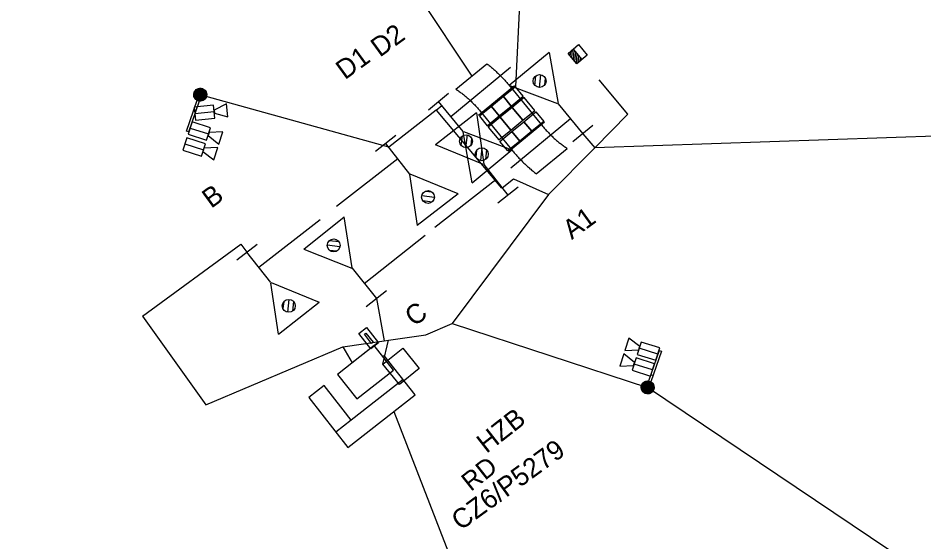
# Model space of a CAD drawing. Extents: x -651112 to -650977, y -1098325 to -1098185.
# Drawn here: x -651091.5 to -651021.5, y -1098284.8 to -1098244.3 of the extents above; entities that cross this region are included whole.
import ezdxf

# ---------------------------------------------------------------- set-up
doc = ezdxf.new("R2010")
doc.units = 0
for name, color, linetype in [('PS 11-01-31', 7, 'Continuous'), ('PS 11-02-41', 7, 'Continuous'), ('SO 01-86-01', 7, 'Continuous'), ('SO 11-13-01', 7, 'Continuous'), ('SO 11-50-01', 7, 'Continuous')]:
    doc.layers.add(name, color=color, linetype=linetype)

msp = doc.modelspace()

# ---------------------------------------------------------------- linework, layer by layer
at = {"layer": 'PS 11-01-31'}
for p, q in [((-651049.004, -1098247.056), (-651048.196, -1098246.386)), ((-651049.004, -1098247.056), (-651048.6, -1098246.721)), ((-651049.004, -1098247.056), (-651048.6, -1098246.721)), ((-651048.709, -1098247.412), (-651048.648, -1098246.761)), ((-651048.6, -1098246.721), (-651047.93, -1098247.53)), ((-651048.6, -1098246.721), (-651047.93, -1098247.53)), ((-651048.196, -1098246.386), (-651047.525, -1098247.195)), ((-651050.456, -1098246.985), (-651053.538, -1098249.535)), ((-651050.456, -1098246.985), (-651049.766, -1098250.925)), ((-651048.334, -1098247.865), (-651049.004, -1098247.056)), ((-651048.334, -1098247.865), (-651049.004, -1098247.056)), ((-651048.334, -1098247.865), (-651049.004, -1098247.056)), ((-651048.946, -1098247.126), (-651048.934, -1098246.998)), ((-651048.827, -1098247.27), (-651048.791, -1098246.88)), ((-651048.59, -1098247.555), (-651048.521, -1098246.816)), ((-651048.472, -1098247.698), (-651048.403, -1098246.959)), ((-651048.353, -1098247.841), (-651048.284, -1098247.102)), ((-651047.525, -1098247.195), (-651048.334, -1098247.865)), ((-651048.215, -1098247.766), (-651048.166, -1098247.245)), ((-651048.072, -1098247.647), (-651048.048, -1098247.387)), ((-651058.06, -1098251.939), (-651053.436, -1098248.116)), ((-651047.93, -1098247.53), (-651048.334, -1098247.865)), ((-651047.93, -1098247.53), (-651048.334, -1098247.865)), ((-651051.562, -1098249.539), (-651051.491, -1098248.791)), ((-651051.2, -1098249.693), (-651051.106, -1098248.707)), ((-651049.798, -1098250.954), (-651053.538, -1098249.535)), ((-651050.805, -1098249.498), (-651050.755, -1098248.975)), ((-651044.373, -1098251.75), (-651046.585, -1098249.116)), ((-651059.787, -1098251.42), (-651058.245, -1098250.146)), ((-651057.105, -1098253.095), (-651059.016, -1098250.783)), ((-651049.766, -1098250.957), (-651047.854, -1098253.269)), ((-651059.188, -1098251.441), (-651062.859, -1098254.301)), ((-651056.078, -1098251.663), (-651059.229, -1098254.128)), ((-651059.184, -1098251.442), (-651058.764, -1098251.093)), ((-651059.184, -1098251.442), (-651054.14, -1098257.484)), ((-651056.078, -1098251.663), (-651055.496, -1098255.62)), ((-651048.81, -1098252.113), (-651053.433, -1098255.937)), ((-651046.938, -1098254.352), (-651044.373, -1098251.75)), ((-651047.083, -1098252.631), (-651048.624, -1098253.906)), ((-651062.296, -1098253.406), (-651063.871, -1098254.638)), ((-651057.253, -1098254.186), (-651057.162, -1098253.44)), ((-651056.416, -1098257.067), (-651057.104, -1098253.127)), ((-651057.072, -1098253.098), (-651053.333, -1098254.518)), ((-651056.896, -1098254.349), (-651056.776, -1098253.366)), ((-651056.496, -1098254.166), (-651056.432, -1098253.643)), ((-651047.854, -1098253.269), (-651046.938, -1098254.352)), ((-651019.677, -1098253.419), (-651046.938, -1098254.352)), ((-651061.234, -1098256.384), (-651063.083, -1098254.022)), ((-651055.529, -1098255.648), (-651059.229, -1098254.128)), ((-651055.671, -1098254.36), (-651055.765, -1098255.345)), ((-651050.505, -1098257.97), (-651046.938, -1098254.352)), ((-651056.416, -1098257.067), (-651053.333, -1098254.518)), ((-651056.066, -1098254.554), (-651056.116, -1098255.077)), ((-651055.309, -1098254.513), (-651055.38, -1098255.261)), ((-651062.159, -1098255.203), (-651066.884, -1098258.901)), ((-651055.497, -1098255.652), (-651053.648, -1098258.015)), ((-651061.238, -1098256.417), (-651060.652, -1098260.373)), ((-651057.502, -1098257.908), (-651061.204, -1098256.391)), ((-651054.573, -1098256.833), (-651059.298, -1098260.53)), ((-651054.083, -1098257.463), (-651053.21, -1098256.76)), ((-651053.21, -1098256.76), (-651050.505, -1098257.97)), ((-651057.502, -1098257.908), (-651060.652, -1098260.373)), ((-651060.032, -1098257.711), (-651059.51, -1098257.775)), ((-651050.505, -1098257.97), (-651057.947, -1098267.94)), ((-651052.861, -1098257.398), (-651054.436, -1098258.631)), ((-651060.306, -1098258.055), (-651059.323, -1098258.175)), ((-651060.233, -1098258.442), (-651059.488, -1098258.533)), ((-651072.886, -1098263.596), (-651068.16, -1098259.899)), ((-651069.424, -1098262.182), (-651066.297, -1098259.687)), ((-651065.674, -1098263.638), (-651066.297, -1098259.687)), ((-651064.742, -1098264.843), (-651060.052, -1098261.101)), ((-651081.875, -1098267.363), (-651074.288, -1098261.815)), ((-651074.598, -1098263.031), (-651073.023, -1098261.799)), ((-651074.288, -1098261.815), (-651073.81, -1098262.415)), ((-651069.424, -1098262.182), (-651065.708, -1098263.664)), ((-651066.621, -1098262.008), (-651067.605, -1098261.897)), ((-651066.697, -1098261.622), (-651067.444, -1098261.538)), ((-651071.962, -1098264.778), (-651073.81, -1098262.415)), ((-651066.892, -1098262.355), (-651067.415, -1098262.296)), ((-651065.677, -1098263.67), (-651063.807, -1098266.015)), ((-651071.38, -1098268.767), (-651071.962, -1098264.81)), ((-651071.929, -1098264.782), (-651068.23, -1098266.302)), ((-651064.588, -1098266.639), (-651063.025, -1098265.392)), ((-651071.38, -1098268.767), (-651068.23, -1098266.302)), ((-651070.963, -1098266.264), (-651071.027, -1098266.786)), ((-651070.563, -1098266.081), (-651070.683, -1098267.063)), ((-651070.205, -1098266.244), (-651070.296, -1098266.989)), ((-651063.807, -1098266.015), (-651063.212, -1098269.281)), ((-651081.875, -1098267.363), (-651076.998, -1098274.237)), ((-651059.998, -1098268.811), (-651057.947, -1098267.94)), ((-651057.947, -1098267.94), (-651057.947, -1098267.94)), ((-651062.885, -1098269.233), (-651059.998, -1098268.811)), ((-651076.998, -1098274.237), (-651066.397, -1098269.747)), ((-651063.972, -1098269.653), (-651066.807, -1098271.871)), ((-651066.397, -1098269.747), (-651063.212, -1098269.281)), ((-651066.397, -1098269.747), (-651065.667, -1098270.979)), ((-651063.676, -1098269.422), (-651065.667, -1098270.979)), ((-651062.493, -1098271.543), (-651063.972, -1098269.653)), ((-651063.21, -1098269.28), (-651062.884, -1098269.233)), ((-651066.807, -1098271.871), (-651065.328, -1098273.761)), ((-651065.328, -1098273.761), (-651062.493, -1098271.543))]:
    msp.add_line(p, q, dxfattribs=at)
for centre in [(-651051.2, -1098249.196), (-651056.883, -1098253.852), (-651055.671, -1098254.856), (-651059.821, -1098258.162), (-651067.107, -1098261.906), (-651070.576, -1098266.577)]:
    msp.add_circle(centre, 0.5, dxfattribs=at)
at = {"layer": 'PS 11-02-41'}
for p, q in [((-651062.859, -1098254.301), (-651077.417, -1098250.253)), ((-651078.478, -1098253.061), (-651077.661, -1098250.677)), ((-651078.302, -1098253.121), (-651077.485, -1098250.737)), ((-651077.83, -1098251.169), (-651077.654, -1098251.229)), ((-651077.825, -1098251.715), (-651076.333, -1098251.561)), ((-651076.331, -1098251.583), (-651076.335, -1098251.54)), ((-651076.335, -1098251.546), (-651076.332, -1098251.577)), ((-651078.302, -1098253.121), (-651078.478, -1098253.061)), ((-651078.198, -1098252.832), (-651076.769, -1098253.288)), ((-651076.775, -1098253.308), (-651076.763, -1098253.268)), ((-651076.764, -1098253.273), (-651076.774, -1098253.303)), ((-651078.598, -1098254.06), (-651077.169, -1098254.516)), ((-651077.175, -1098254.536), (-651077.163, -1098254.496)), ((-651077.164, -1098254.501), (-651077.174, -1098254.531)), ((-651057.947, -1098267.94), (-651042.851, -1098272.885)), ((-651063.307, -1098271.08), (-651062.884, -1098269.233)), ((-651043.493, -1098269.828), (-651043.506, -1098269.869)), ((-651043.505, -1098269.864), (-651043.495, -1098269.833)), ((-651042.071, -1098270.305), (-651043.5, -1098269.849)), ((-651041.966, -1098270.017), (-651042.783, -1098272.401)), ((-651041.789, -1098270.077), (-651042.607, -1098272.461)), ((-651041.966, -1098270.017), (-651041.789, -1098270.077)), ((-651043.893, -1098271.057), (-651043.906, -1098271.098)), ((-651043.905, -1098271.093), (-651043.895, -1098271.062)), ((-651042.471, -1098271.534), (-651043.9, -1098271.078)), ((-651042.438, -1098271.969), (-651042.614, -1098271.909)), ((-650996.009, -1098304.415), (-651042.851, -1098272.885))]:
    msp.add_line(p, q, dxfattribs=at)
for points in [[(-651077.792, -1098249.922), (-651077.9, -1098250.381), (-651077.916, -1098250.284), (-651077.792, -1098249.922)], [(-651077.792, -1098249.922), (-651077.916, -1098250.284), (-651077.849, -1098250.002), (-651077.792, -1098249.922)], [(-651077.849, -1098250.002), (-651077.916, -1098250.284), (-651077.912, -1098250.186), (-651077.849, -1098250.002)], [(-651077.849, -1098250.002), (-651077.912, -1098250.186), (-651077.89, -1098250.091), (-651077.849, -1098250.002)], [(-651077.72, -1098249.855), (-651077.866, -1098250.473), (-651077.9, -1098250.381), (-651077.72, -1098249.855)], [(-651077.72, -1098249.855), (-651077.9, -1098250.381), (-651077.792, -1098249.922), (-651077.72, -1098249.855)], [(-651077.637, -1098249.804), (-651077.815, -1098250.556), (-651077.866, -1098250.473), (-651077.637, -1098249.804)], [(-651077.637, -1098249.804), (-651077.866, -1098250.473), (-651077.72, -1098249.855), (-651077.637, -1098249.804)], [(-651077.545, -1098249.77), (-651077.748, -1098250.628), (-651077.815, -1098250.556), (-651077.545, -1098249.77)], [(-651077.545, -1098249.77), (-651077.815, -1098250.556), (-651077.637, -1098249.804), (-651077.545, -1098249.77)], [(-651077.448, -1098249.754), (-651077.668, -1098250.685), (-651077.748, -1098250.628), (-651077.448, -1098249.754)], [(-651077.448, -1098249.754), (-651077.748, -1098250.628), (-651077.545, -1098249.77), (-651077.448, -1098249.754)], [(-651077.35, -1098249.757), (-651077.668, -1098250.685), (-651077.448, -1098249.754), (-651077.35, -1098249.757)], [(-651077.35, -1098249.757), (-651077.579, -1098250.726), (-651077.668, -1098250.685), (-651077.35, -1098249.757)], [(-651077.255, -1098249.78), (-651077.579, -1098250.726), (-651077.35, -1098249.757), (-651077.255, -1098249.78)], [(-651077.255, -1098249.78), (-651077.484, -1098250.749), (-651077.579, -1098250.726), (-651077.255, -1098249.78)], [(-651077.166, -1098249.821), (-651077.484, -1098250.749), (-651077.255, -1098249.78), (-651077.166, -1098249.821)], [(-651077.166, -1098249.821), (-651077.386, -1098250.752), (-651077.484, -1098250.749), (-651077.166, -1098249.821)], [(-651077.086, -1098249.878), (-651077.386, -1098250.752), (-651077.166, -1098249.821), (-651077.086, -1098249.878)], [(-651077.086, -1098249.878), (-651077.289, -1098250.736), (-651077.386, -1098250.752), (-651077.086, -1098249.878)], [(-651077.019, -1098249.95), (-651077.289, -1098250.736), (-651077.086, -1098249.878), (-651077.019, -1098249.95)], [(-651077.019, -1098249.95), (-651077.197, -1098250.702), (-651077.289, -1098250.736), (-651077.019, -1098249.95)], [(-651076.968, -1098250.033), (-651077.197, -1098250.702), (-651077.019, -1098249.95), (-651076.968, -1098250.033)], [(-651076.968, -1098250.033), (-651077.114, -1098250.651), (-651077.197, -1098250.702), (-651076.968, -1098250.033)], [(-651076.934, -1098250.125), (-651077.114, -1098250.651), (-651076.968, -1098250.033), (-651076.934, -1098250.125)], [(-651076.934, -1098250.125), (-651077.042, -1098250.584), (-651077.114, -1098250.651), (-651076.934, -1098250.125)], [(-651076.918, -1098250.222), (-651077.042, -1098250.584), (-651076.934, -1098250.125), (-651076.918, -1098250.222)], [(-651076.918, -1098250.222), (-651076.985, -1098250.504), (-651077.042, -1098250.584), (-651076.918, -1098250.222)], [(-651076.921, -1098250.32), (-651076.985, -1098250.504), (-651076.918, -1098250.222), (-651076.921, -1098250.32)], [(-651076.921, -1098250.32), (-651076.944, -1098250.415), (-651076.985, -1098250.504), (-651076.921, -1098250.32)], [(-651076.346, -1098251.437), (-651076.32, -1098251.686), (-651075.287, -1098251.956), (-651075.39, -1098250.962), (-651076.346, -1098251.437)], [(-651077.877, -1098251.218), (-651077.774, -1098252.212), (-651076.282, -1098252.059), (-651076.384, -1098251.064), (-651077.877, -1098251.218)], [(-651077.877, -1098251.218), (-651077.774, -1098252.212), (-651076.282, -1098252.059), (-651076.384, -1098251.064), (-651077.877, -1098251.218)], [(-651078.046, -1098252.356), (-651078.35, -1098253.308), (-651076.921, -1098253.765), (-651076.617, -1098252.812), (-651078.046, -1098252.356)], [(-651078.046, -1098252.356), (-651078.35, -1098253.308), (-651076.921, -1098253.765), (-651076.617, -1098252.812), (-651078.046, -1098252.356)], [(-651078.446, -1098253.584), (-651078.75, -1098254.536), (-651077.321, -1098254.993), (-651077.017, -1098254.04), (-651078.446, -1098253.584)], [(-651078.446, -1098253.584), (-651078.75, -1098254.536), (-651077.321, -1098254.993), (-651077.017, -1098254.04), (-651078.446, -1098253.584)], [(-651076.731, -1098253.169), (-651076.807, -1098253.407), (-651075.969, -1098254.069), (-651075.664, -1098253.116), (-651076.731, -1098253.169)], [(-651077.131, -1098254.397), (-651077.207, -1098254.635), (-651076.369, -1098255.297), (-651076.064, -1098254.344), (-651077.131, -1098254.397)], [(-651043.538, -1098269.968), (-651043.462, -1098269.729), (-651044.3, -1098269.068), (-651044.604, -1098270.021), (-651043.538, -1098269.968)], [(-651063.307, -1098271.08), (-651061.771, -1098269.847), (-651060.5, -1098271.429), (-651062.035, -1098272.663), (-651063.307, -1098271.08)], [(-651042.223, -1098270.781), (-651041.919, -1098269.829), (-651043.348, -1098269.372), (-651043.652, -1098270.325), (-651042.223, -1098270.781)], [(-651042.223, -1098270.781), (-651041.919, -1098269.829), (-651043.348, -1098269.372), (-651043.652, -1098270.325), (-651042.223, -1098270.781)], [(-651043.938, -1098271.197), (-651043.862, -1098270.958), (-651044.7, -1098270.297), (-651045.004, -1098271.25), (-651043.938, -1098271.197)], [(-651042.623, -1098272.01), (-651042.319, -1098271.058), (-651043.748, -1098270.601), (-651044.052, -1098271.554), (-651042.623, -1098272.01)], [(-651042.623, -1098272.01), (-651042.319, -1098271.058), (-651043.748, -1098270.601), (-651044.052, -1098271.554), (-651042.623, -1098272.01)], [(-651043.35, -1098272.916), (-651043.283, -1098272.634), (-651043.226, -1098272.554), (-651043.35, -1098272.916)], [(-651043.35, -1098272.916), (-651043.226, -1098272.554), (-651043.334, -1098273.013), (-651043.35, -1098272.916)], [(-651043.346, -1098272.818), (-651043.283, -1098272.634), (-651043.35, -1098272.916), (-651043.346, -1098272.818)], [(-651043.346, -1098272.818), (-651043.324, -1098272.723), (-651043.283, -1098272.634), (-651043.346, -1098272.818)], [(-651043.334, -1098273.013), (-651043.226, -1098272.554), (-651043.154, -1098272.487), (-651043.334, -1098273.013)], [(-651043.334, -1098273.013), (-651043.154, -1098272.487), (-651043.3, -1098273.105), (-651043.334, -1098273.013)], [(-651043.3, -1098273.105), (-651043.154, -1098272.487), (-651043.071, -1098272.436), (-651043.3, -1098273.105)], [(-651043.3, -1098273.105), (-651043.071, -1098272.436), (-651043.248, -1098273.188), (-651043.3, -1098273.105)], [(-651043.248, -1098273.188), (-651043.071, -1098272.436), (-651042.979, -1098272.401), (-651043.248, -1098273.188)], [(-651043.248, -1098273.188), (-651042.979, -1098272.401), (-651043.182, -1098273.26), (-651043.248, -1098273.188)], [(-651043.182, -1098273.26), (-651042.979, -1098272.401), (-651042.882, -1098272.386), (-651043.182, -1098273.26)], [(-651043.182, -1098273.26), (-651042.882, -1098272.386), (-651043.102, -1098273.317), (-651043.182, -1098273.26)], [(-651043.102, -1098273.317), (-651042.882, -1098272.386), (-651042.784, -1098272.389), (-651043.102, -1098273.317)], [(-651043.102, -1098273.317), (-651042.784, -1098272.389), (-651043.013, -1098273.358), (-651043.102, -1098273.317)], [(-651043.013, -1098273.358), (-651042.784, -1098272.389), (-651042.689, -1098272.412), (-651043.013, -1098273.358)], [(-651043.013, -1098273.358), (-651042.689, -1098272.412), (-651042.918, -1098273.38), (-651043.013, -1098273.358)], [(-651042.918, -1098273.38), (-651042.689, -1098272.412), (-651042.6, -1098272.453), (-651042.918, -1098273.38)], [(-651042.918, -1098273.38), (-651042.6, -1098272.453), (-651042.82, -1098273.384), (-651042.918, -1098273.38)], [(-651042.82, -1098273.384), (-651042.6, -1098272.453), (-651042.52, -1098272.51), (-651042.82, -1098273.384)], [(-651042.82, -1098273.384), (-651042.52, -1098272.51), (-651042.723, -1098273.368), (-651042.82, -1098273.384)], [(-651042.723, -1098273.368), (-651042.52, -1098272.51), (-651042.453, -1098272.582), (-651042.723, -1098273.368)], [(-651042.723, -1098273.368), (-651042.453, -1098272.582), (-651042.631, -1098273.334), (-651042.723, -1098273.368)], [(-651042.631, -1098273.334), (-651042.453, -1098272.582), (-651042.402, -1098272.665), (-651042.631, -1098273.334)], [(-651042.631, -1098273.334), (-651042.402, -1098272.665), (-651042.548, -1098273.282), (-651042.631, -1098273.334)], [(-651042.548, -1098273.282), (-651042.402, -1098272.665), (-651042.367, -1098272.757), (-651042.548, -1098273.282)], [(-651042.548, -1098273.282), (-651042.367, -1098272.757), (-651042.476, -1098273.216), (-651042.548, -1098273.282)], [(-651042.476, -1098273.216), (-651042.367, -1098272.757), (-651042.352, -1098272.854), (-651042.476, -1098273.216)], [(-651042.476, -1098273.216), (-651042.352, -1098272.854), (-651042.419, -1098273.136), (-651042.476, -1098273.216)], [(-651042.419, -1098273.136), (-651042.352, -1098272.854), (-651042.355, -1098272.952), (-651042.419, -1098273.136)], [(-651042.419, -1098273.136), (-651042.355, -1098272.952), (-651042.378, -1098273.047), (-651042.419, -1098273.136)]]:
    msp.add_lwpolyline(points, dxfattribs=at)
for centre in [(-651077.417, -1098250.253), (-651042.851, -1098272.885)]:
    msp.add_circle(centre, 0.5, dxfattribs=at)
at = {"layer": 'SO 01-86-01'}
for p, q in [((-651065.156, -1098268.718), (-651064.565, -1098268.256)), ((-651064.565, -1098268.256), (-651063.641, -1098269.438)), ((-651064.231, -1098269.9), (-651065.156, -1098268.718)), ((-651064.735, -1098268.77), (-651064.616, -1098268.677)), ((-651064.18, -1098269.479), (-651064.735, -1098268.77)), ((-651064.616, -1098268.677), (-651064.062, -1098269.386)), ((-651063.641, -1098269.438), (-651064.231, -1098269.9)), ((-651064.062, -1098269.386), (-651064.18, -1098269.479)), ((-651060.818, -1098273.451), (-651063.221, -1098270.379)), ((-651061.742, -1098272.269), (-651065.759, -1098275.412)), ((-651067.854, -1098272.734), (-651069.032, -1098273.663)), ((-651066.375, -1098274.625), (-651067.854, -1098272.734)), ((-651069.032, -1098273.663), (-651066.016, -1098277.518)), ((-651066.016, -1098277.518), (-651060.818, -1098273.451)), ((-651062.469, -1098274.743), (-651060.818, -1098273.451)), ((-651065.759, -1098275.412), (-651066.375, -1098274.625)), ((-651062.469, -1098274.743), (-651055.984, -1098291.407)), ((-651065.759, -1098275.412), (-651066.94, -1098276.336))]:
    msp.add_line(p, q, dxfattribs=at)
at = {"layer": 'SO 11-13-01'}
msp.add_line((-651091.488, -1098195.729), (-651056.443, -1098248.82), dxfattribs=at)
for points in [[(-651057.668, -1098249.824), (-651055.269, -1098247.859)], [(-651055.269, -1098247.859), (-651055.269, -1098247.859), (-651055.208, -1098247.908), (-651055.146, -1098247.957), (-651055.085, -1098248.007), (-651055.024, -1098248.057), (-651054.964, -1098248.107), (-651054.904, -1098248.158), (-651054.844, -1098248.21), (-651054.785, -1098248.261), (-651054.726, -1098248.313), (-651054.667, -1098248.366), (-651054.609, -1098248.419), (-651054.551, -1098248.472), (-651054.493, -1098248.526), (-651054.436, -1098248.58), (-651054.379, -1098248.635), (-651054.323, -1098248.69), (-651054.267, -1098248.745), (-651054.211, -1098248.801), (-651054.156, -1098248.857), (-651054.101, -1098248.913), (-651054.046, -1098248.97), (-651053.992, -1098249.027), (-651053.938, -1098249.085), (-651053.885, -1098249.143), (-651053.832, -1098249.201), (-651053.779, -1098249.259), (-651053.727, -1098249.318), (-651053.675, -1098249.378), (-651053.624, -1098249.437), (-651053.573, -1098249.498), (-651053.523, -1098249.558), (-651053.473, -1098249.619), (-651050.938, -1098252.713), (-651050.887, -1098252.774), (-651050.836, -1098252.835), (-651050.784, -1098252.895), (-651050.732, -1098252.955), (-651050.679, -1098253.014), (-651050.626, -1098253.073), (-651050.572, -1098253.131), (-651050.518, -1098253.188), (-651050.463, -1098253.246), (-651050.407, -1098253.302), (-651050.351, -1098253.358), (-651050.295, -1098253.414), (-651050.238, -1098253.469), (-651050.18, -1098253.524), (-651050.122, -1098253.578), (-651050.064, -1098253.631), (-651050.005, -1098253.684), (-651049.945, -1098253.736), (-651049.885, -1098253.788), (-651049.824, -1098253.839), (-651049.763, -1098253.89), (-651049.702, -1098253.94), (-651049.64, -1098253.99), (-651049.578, -1098254.039)], [(-651057.668, -1098249.824), (-651057.668, -1098249.824), (-651057.602, -1098249.868), (-651057.537, -1098249.913), (-651057.472, -1098249.958), (-651057.407, -1098250.004), (-651057.343, -1098250.051), (-651057.279, -1098250.098), (-651057.216, -1098250.146), (-651057.153, -1098250.194), (-651057.091, -1098250.243), (-651057.029, -1098250.293), (-651056.968, -1098250.343), (-651056.907, -1098250.393), (-651056.846, -1098250.445), (-651056.786, -1098250.497), (-651056.726, -1098250.549), (-651056.667, -1098250.602), (-651056.609, -1098250.655), (-651056.551, -1098250.709), (-651056.493, -1098250.764), (-651056.436, -1098250.819), (-651056.38, -1098250.874), (-651056.324, -1098250.931), (-651056.268, -1098250.987), (-651056.213, -1098251.044), (-651056.159, -1098251.102), (-651056.105, -1098251.16), (-651056.052, -1098251.219), (-651055.999, -1098251.278), (-651055.947, -1098251.338), (-651055.895, -1098251.398), (-651055.844, -1098251.459), (-651055.793, -1098251.52), (-651053.259, -1098254.614), (-651053.208, -1098254.675), (-651053.158, -1098254.735), (-651053.107, -1098254.795), (-651053.056, -1098254.855), (-651053.004, -1098254.914), (-651052.952, -1098254.973), (-651052.899, -1098255.032), (-651052.846, -1098255.09), (-651052.793, -1098255.148), (-651052.739, -1098255.206), (-651052.685, -1098255.263), (-651052.63, -1098255.32), (-651052.575, -1098255.376), (-651052.52, -1098255.432), (-651052.464, -1098255.488), (-651052.408, -1098255.543), (-651052.352, -1098255.598), (-651052.295, -1098255.653), (-651052.238, -1098255.707), (-651052.18, -1098255.761), (-651052.122, -1098255.814), (-651052.064, -1098255.867), (-651052.005, -1098255.919), (-651051.946, -1098255.972)], [(-651051.462, -1098256.374), (-651049.063, -1098254.409)], [(-651049.578, -1098254.039), (-651049.515, -1098254.087), (-651049.452, -1098254.135), (-651049.388, -1098254.182), (-651049.324, -1098254.229), (-651049.259, -1098254.275), (-651049.194, -1098254.32), (-651049.129, -1098254.365), (-651049.063, -1098254.409), (-651049.063, -1098254.409)], [(-651051.946, -1098255.972), (-651051.887, -1098256.023), (-651051.827, -1098256.075), (-651051.767, -1098256.126), (-651051.707, -1098256.176), (-651051.646, -1098256.226), (-651051.585, -1098256.276), (-651051.523, -1098256.325), (-651051.462, -1098256.374), (-651051.462, -1098256.374)]]:
    msp.add_lwpolyline(points, dxfattribs=at)
at = {"layer": 'SO 11-50-01'}
msp.add_line((-651050.336, -1098195.104), (-651053.069, -1098249.637), dxfattribs=at)
for points in [[(-651053.126, -1098249.568), (-651055.911, -1098251.849)], [(-651053.396, -1098251.133), (-651052.467, -1098250.372), (-651053.069, -1098249.637), (-651053.998, -1098250.398), (-651053.396, -1098251.133)], [(-651054.324, -1098251.893), (-651053.396, -1098251.133), (-651053.998, -1098250.398), (-651054.926, -1098251.158), (-651054.324, -1098251.893)], [(-651052.494, -1098252.233), (-651051.566, -1098251.473), (-651052.38, -1098250.479), (-651053.309, -1098251.239), (-651052.494, -1098252.233)], [(-651055.252, -1098252.654), (-651054.324, -1098251.893), (-651054.926, -1098251.158), (-651055.854, -1098251.919), (-651055.252, -1098252.654)], [(-651053.423, -1098252.994), (-651052.494, -1098252.233), (-651053.309, -1098251.239), (-651054.237, -1098252), (-651053.423, -1098252.994)], [(-651052.407, -1098252.34), (-651051.479, -1098251.579), (-651050.877, -1098252.314), (-651051.805, -1098253.075), (-651052.407, -1098252.34)], [(-651054.351, -1098253.754), (-651053.423, -1098252.994), (-651054.237, -1098252), (-651055.165, -1098252.76), (-651054.351, -1098253.754)], [(-651050.82, -1098252.384), (-651053.605, -1098254.665)], [(-651053.335, -1098253.1), (-651052.407, -1098252.34), (-651051.805, -1098253.075), (-651052.733, -1098253.835), (-651053.335, -1098253.1)], [(-651054.264, -1098253.86), (-651053.335, -1098253.1), (-651052.733, -1098253.835), (-651053.662, -1098254.595), (-651054.264, -1098253.86)]]:
    msp.add_lwpolyline(points, dxfattribs=at)

# ---------------------------------------------------------------- texts
at = {"layer": 'PS 11-01-31'}
for s, height, rotation, p in [('D2', 1.5, 36.04406, (-651063.541, -1098247.401)), ('D1', 1.5, 36.04406, (-651066.237, -1098249.142)), ('B', 1.5, 36.04406, (-651076.571, -1098259.084)), ('A1', 1.5, 36.04406, (-651048.713, -1098261.499)), ('C', 1.5, 36.04406, (-651060.909, -1098268.222)), ('CZ6/P5279', 1.5, 36.04406, (-651057.309, -1098283.99)), ('RD', 1.44, 38.24751, (-651056.514, -1098280.972))]:
    msp.add_text(s, height=height, rotation=rotation, dxfattribs=at).set_placement(p)
at = {"layer": 'SO 01-86-01'}
msp.add_text('HZB', height=1.5, rotation=38.03998, dxfattribs=at).set_placement((-651055.308, -1098278.027))

doc.saveas('drawing.dxf')
